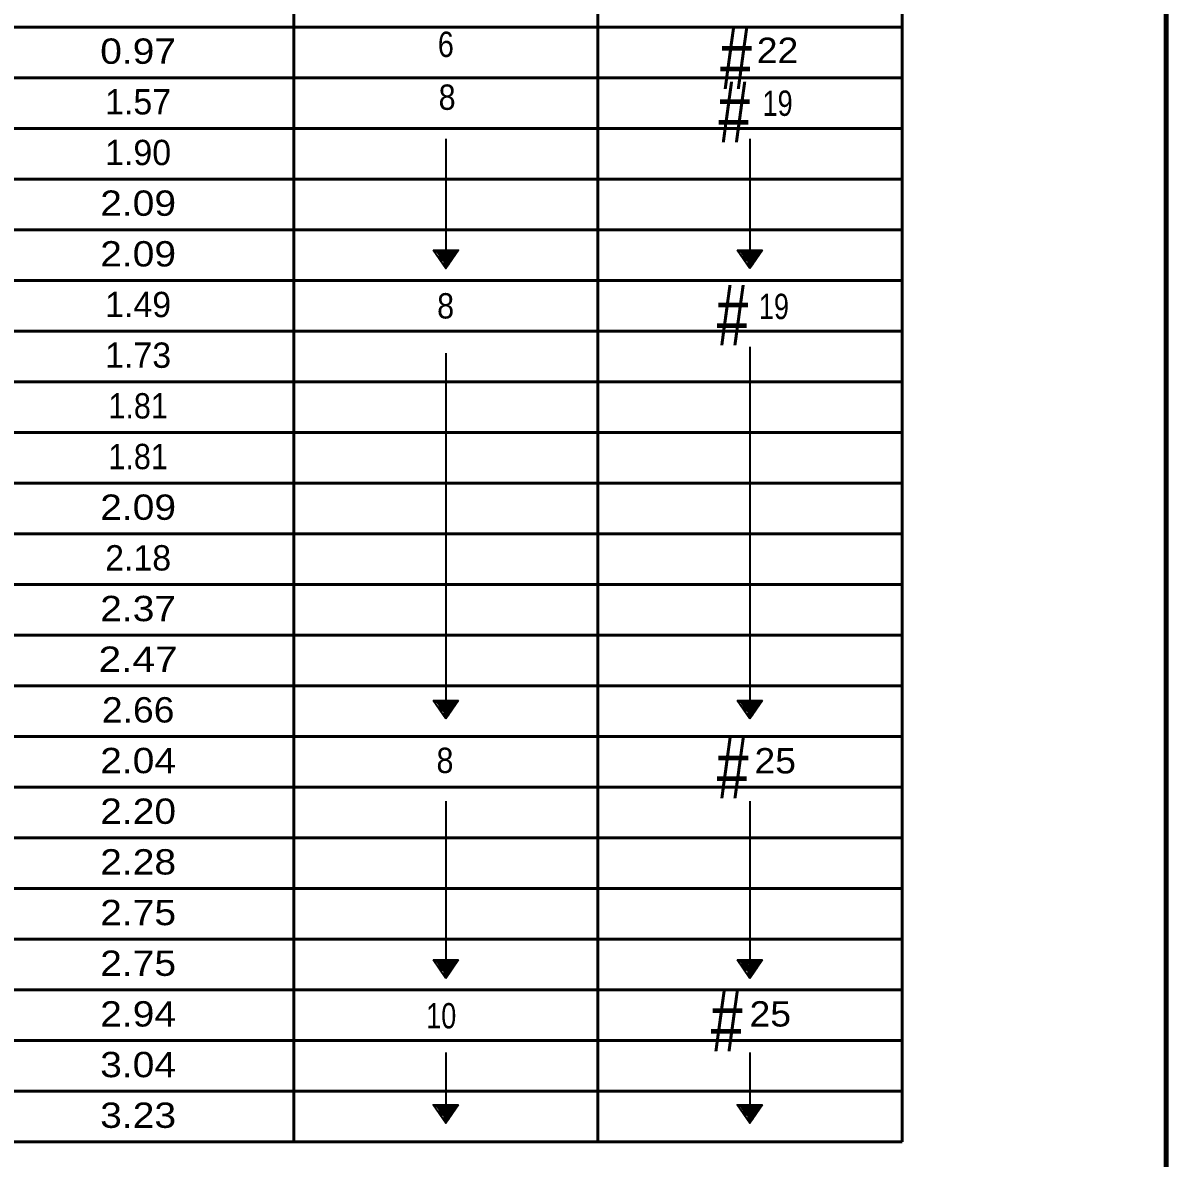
# Model space of a CAD drawing. Extents: x -711 to 145, y 25 to 569.
# Drawn here: x 13 to 138.1, y 280.2 to 404.4 of the extents above; entities that cross this region are included whole.
import ezdxf
from ezdxf.enums import TextEntityAlignment as Align

# ---------------------------------------------------------------- set-up
doc = ezdxf.new("R2010")
doc.units = 0
doc.header["$LTSCALE"] = 1.1
doc.layers.add('1', color=7, linetype='Continuous', lineweight=53)

msp = doc.modelspace()

# ---------------------------------------------------------------- linework, layer by layer
at = {"layer": '1', "lineweight": 158}
msp.add_line((138.105, 36.575), (138.105, 562.675), dxfattribs=at)
at = {"layer": '1', "lineweight": 13}
msp.add_line((138.105, 36.575), (138.105, 562.675), dxfattribs=at)
at = {"layer": '1'}
for p, q in [((42.685, 521.717), (42.685, 281.939)), ((109.213, 521.717), (109.213, 281.939)), ((75.949, 509.936), (75.949, 281.939)), ((-251.147, 403.907), (109.194, 403.907)), ((-251.147, 398.363), (109.194, 398.363)), ((-251.147, 392.819), (109.194, 392.819)), ((-251.147, 387.275), (109.194, 387.275)), ((-251.147, 381.731), (109.194, 381.731)), ((-251.147, 376.187), (109.194, 376.187)), ((-251.147, 370.643), (109.194, 370.643)), ((-251.147, 365.099), (109.194, 365.099)), ((-251.147, 359.555), (109.194, 359.555)), ((-251.147, 354.011), (109.194, 354.011)), ((-251.147, 348.467), (109.194, 348.467)), ((-251.147, 342.923), (109.194, 342.923)), ((-251.147, 337.379), (109.194, 337.379)), ((-251.147, 331.835), (109.194, 331.835)), ((-251.147, 326.291), (109.194, 326.291)), ((-251.147, 320.747), (109.194, 320.747)), ((-251.147, 315.203), (109.194, 315.203)), ((-251.147, 309.659), (109.194, 309.659)), ((-251.147, 304.115), (109.194, 304.115)), ((-251.147, 298.571), (109.194, 298.571)), ((-251.147, 293.027), (109.194, 293.027)), ((-251.147, 287.483), (109.194, 287.483)), ((-251.147, 281.939), (109.213, 281.939))]:
    msp.add_line(p, q, dxfattribs=at)
at = {"layer": '1', "lineweight": 35}
for p, q in [((59.317, 391.691), (59.317, 377.505)), ((92.581, 391.691), (92.581, 377.505)), ((91.195, 379.518), (93.967, 379.518)), ((92.581, 377.505), (91.195, 379.518)), ((93.967, 379.518), (92.581, 377.505)), ((92.581, 368.941), (92.581, 328.233)), ((59.317, 368.222), (59.317, 328.233)), ((57.931, 330.246), (60.703, 330.246)), ((59.317, 328.233), (57.931, 330.246)), ((60.703, 330.246), (59.317, 328.233)), ((91.195, 330.246), (93.967, 330.246)), ((92.581, 328.233), (91.195, 330.246)), ((93.967, 330.246), (92.581, 328.233)), ((59.317, 319.202), (59.317, 301.842)), ((92.581, 319.202), (92.581, 299.829)), ((59.317, 299.829), (57.931, 301.842)), ((57.931, 301.842), (60.703, 301.842)), ((60.703, 301.842), (59.317, 299.829)), ((92.581, 299.829), (91.195, 301.842)), ((91.195, 301.842), (93.967, 301.842)), ((93.967, 301.842), (92.581, 299.829)), ((59.317, 291.713), (59.317, 283.99)), ((92.581, 291.713), (92.581, 283.99))]:
    msp.add_line(p, q, dxfattribs=at)
for points in [[(57.931, 379.518), (60.703, 379.518), (59.317, 377.505)], [(60.703, 286.003), (59.317, 283.99), (57.931, 286.003)], [(93.967, 286.003), (92.581, 283.99), (91.195, 286.003)]]:
    msp.add_lwpolyline(points, close=True, dxfattribs=at)
for points in [[(58.19, 379.32), (58.614, 379.367), (59.273, 379.226), (59.744, 379.32), (59.933, 379.32), (60.216, 379.414), (60.404, 379.367), (59.556, 379.179), (59.179, 379.508), (59.226, 379.179), (59.226, 379.273), (59.65, 379.414), (60.168, 379.414), (60.074, 379.32), (59.085, 379.367), (58.708, 379.32), (58.473, 379.226), (58.661, 379.084), (58.755, 378.896), (58.849, 378.707), (58.896, 378.566), (59.038, 378.378), (59.462, 378.048), (59.462, 377.765), (59.32, 378.048), (59.226, 378.283), (59.038, 378.519), (58.849, 378.755), (58.567, 378.99), (58.378, 379.32), (58.567, 379.037), (58.661, 378.707), (58.802, 378.519), (58.896, 378.425), (59.132, 378.283), (59.273, 378.189), (59.367, 378.001), (59.415, 377.954), (59.273, 378.001), (59.132, 378.236), (59.132, 378.001), (59.65, 378.142), (60.357, 379.367), (60.404, 379.367), (60.357, 379.179), (60.168, 378.849), (59.98, 378.566), (59.933, 378.566), (59.744, 378.236), (59.603, 377.954), (59.462, 377.765), (59.367, 377.765), (60.451, 379.367), (60.404, 379.226), (60.545, 379.32), (60.357, 379.084), (60.074, 378.755), (59.933, 378.66), (59.744, 378.331), (59.65, 378.283), (59.509, 378.472), (59.32, 378.472), (59.132, 378.472), (59.462, 378.189), (59.415, 378.331), (59.179, 378.189), (59.65, 378.802), (59.556, 378.613), (59.509, 378.519), (59.32, 378.519), (59.132, 378.66), (59.085, 378.943), (58.991, 379.037), (58.896, 379.131), (59.367, 379.273), (59.556, 378.99), (59.603, 379.084), (59.226, 378.896), (59.462, 378.943), (59.744, 379.131), (59.839, 379.037), (59.509, 378.755), (59.509, 379.037), (59.32, 379.226), (58.896, 379.084), (58.802, 378.519), (59.367, 378.99), (59.603, 378.943), (59.744, 379.037), (59.886, 379.179), (59.697, 378.707), (59.65, 378.425), (59.98, 378.849), (59.744, 378.802), (60.027, 379.179), (59.886, 378.99), (59.839, 378.943), (59.556, 378.66), (59.509, 378.707), (59.415, 378.896), (59.367, 379.131)], [(59.367, 379.131), (59.038, 378.896), (59.226, 378.755), (58.661, 379.084), (58.661, 379.179), (58.943, 378.707), (59.415, 378.755), (59.179, 378.613), (59.462, 378.66), (59.886, 379.084), (60.121, 379.131), (60.121, 379.179), (59.98, 378.896), (59.556, 378.378), (59.462, 378.001), (58.755, 379.131), (58.755, 379.32), (58.849, 379.131), (58.755, 378.566), (59.273, 378.283), (59.085, 377.812), (59.32, 377.907), (59.132, 378.519), (59.744, 379.131), (59.226, 378.99)], [(91.454, 379.32), (91.878, 379.367), (92.537, 379.226), (93.008, 379.32), (93.197, 379.32), (93.48, 379.414), (93.668, 379.367), (92.82, 379.179), (92.443, 379.508), (92.49, 379.179), (92.49, 379.273), (92.914, 379.414), (93.432, 379.414), (93.338, 379.32), (92.349, 379.367), (91.972, 379.32), (91.737, 379.226), (91.925, 379.084), (92.019, 378.896), (92.113, 378.707), (92.16, 378.566), (92.302, 378.378), (92.726, 378.048), (92.726, 377.765), (92.584, 378.048), (92.49, 378.283), (92.302, 378.519), (92.113, 378.755), (91.831, 378.99), (91.642, 379.32), (91.831, 379.037), (91.925, 378.707), (92.066, 378.519), (92.16, 378.425), (92.396, 378.283), (92.537, 378.189), (92.631, 378.001), (92.679, 377.954), (92.537, 378.001), (92.396, 378.236), (92.396, 378.001), (92.914, 378.142), (93.621, 379.367), (93.668, 379.367), (93.621, 379.179), (93.432, 378.849), (93.244, 378.566), (93.197, 378.566), (93.008, 378.236), (92.867, 377.954), (92.726, 377.765), (92.631, 377.765), (93.715, 379.367), (93.668, 379.226), (93.809, 379.32), (93.621, 379.084), (93.338, 378.755), (93.197, 378.66), (93.008, 378.331), (92.914, 378.283), (92.773, 378.472), (92.584, 378.472), (92.396, 378.472), (92.726, 378.189), (92.679, 378.331), (92.443, 378.189), (92.914, 378.802), (92.82, 378.613), (92.773, 378.519), (92.584, 378.519), (92.396, 378.66), (92.349, 378.943), (92.255, 379.037), (92.16, 379.131), (92.631, 379.273), (92.82, 378.99), (92.867, 379.084), (92.49, 378.896), (92.726, 378.943), (93.008, 379.131), (93.103, 379.037), (92.773, 378.755), (92.773, 379.037), (92.584, 379.226), (92.16, 379.084), (92.066, 378.519), (92.631, 378.99), (92.867, 378.943), (93.008, 379.037), (93.15, 379.179), (92.961, 378.707), (92.914, 378.425), (93.244, 378.849), (93.008, 378.802), (93.291, 379.179), (93.15, 378.99), (93.103, 378.943), (92.82, 378.66), (92.773, 378.707), (92.679, 378.896), (92.631, 379.131)], [(92.631, 379.131), (92.302, 378.896), (92.49, 378.755), (91.925, 379.084), (91.925, 379.179), (92.207, 378.707), (92.679, 378.755), (92.443, 378.613), (92.726, 378.66), (93.15, 379.084), (93.385, 379.131), (93.385, 379.179), (93.244, 378.896), (92.82, 378.378), (92.726, 378.001), (92.019, 379.131), (92.019, 379.32), (92.113, 379.131), (92.019, 378.566), (92.537, 378.283), (92.349, 377.812), (92.584, 377.907), (92.396, 378.519), (93.008, 379.131), (92.49, 378.99)], [(58.19, 330.048), (58.614, 330.095), (59.273, 329.954), (59.744, 330.048), (59.933, 330.048), (60.216, 330.142), (60.404, 330.095), (59.556, 329.907), (59.179, 330.236), (59.226, 329.907), (59.226, 330.001), (59.65, 330.142), (60.168, 330.142), (60.074, 330.048), (59.085, 330.095), (58.708, 330.048), (58.473, 329.954), (58.661, 329.812), (58.755, 329.624), (58.849, 329.435), (58.896, 329.294), (59.038, 329.106), (59.462, 328.776), (59.462, 328.493), (59.32, 328.776), (59.226, 329.011), (59.038, 329.247), (58.849, 329.483), (58.567, 329.718), (58.378, 330.048), (58.567, 329.765), (58.661, 329.435), (58.802, 329.247), (58.896, 329.153), (59.132, 329.011), (59.273, 328.917), (59.367, 328.729), (59.415, 328.682), (59.273, 328.729), (59.132, 328.964), (59.132, 328.729), (59.65, 328.87), (60.357, 330.095), (60.404, 330.095), (60.357, 329.907), (60.168, 329.577), (59.98, 329.294), (59.933, 329.294), (59.744, 328.964), (59.603, 328.682), (59.462, 328.493), (59.367, 328.493), (60.451, 330.095), (60.404, 329.954), (60.545, 330.048), (60.357, 329.812), (60.074, 329.483), (59.933, 329.388), (59.744, 329.059), (59.65, 329.011), (59.509, 329.2), (59.32, 329.2), (59.132, 329.2), (59.462, 328.917), (59.415, 329.059), (59.179, 328.917), (59.65, 329.53), (59.556, 329.341), (59.509, 329.247), (59.32, 329.247), (59.132, 329.388), (59.085, 329.671), (58.991, 329.765), (58.896, 329.859), (59.367, 330.001), (59.556, 329.718), (59.603, 329.812), (59.226, 329.624), (59.462, 329.671), (59.744, 329.859), (59.839, 329.765), (59.509, 329.483), (59.509, 329.765), (59.32, 329.954), (58.896, 329.812), (58.802, 329.247), (59.367, 329.718), (59.603, 329.671), (59.744, 329.765), (59.886, 329.907), (59.697, 329.435), (59.65, 329.153), (59.98, 329.577), (59.744, 329.53), (60.027, 329.907), (59.886, 329.718), (59.839, 329.671), (59.556, 329.388), (59.509, 329.435), (59.415, 329.624), (59.367, 329.859)], [(91.454, 330.048), (91.878, 330.095), (92.537, 329.954), (93.008, 330.048), (93.197, 330.048), (93.48, 330.142), (93.668, 330.095), (92.82, 329.907), (92.443, 330.236), (92.49, 329.907), (92.49, 330.001), (92.914, 330.142), (93.432, 330.142), (93.338, 330.048), (92.349, 330.095), (91.972, 330.048), (91.737, 329.954), (91.925, 329.812), (92.019, 329.624), (92.113, 329.435), (92.16, 329.294), (92.302, 329.106), (92.726, 328.776), (92.726, 328.493), (92.584, 328.776), (92.49, 329.011), (92.302, 329.247), (92.113, 329.483), (91.831, 329.718), (91.642, 330.048), (91.831, 329.765), (91.925, 329.435), (92.066, 329.247), (92.16, 329.153), (92.396, 329.011), (92.537, 328.917), (92.631, 328.729), (92.679, 328.682), (92.537, 328.729), (92.396, 328.964), (92.396, 328.729), (92.914, 328.87), (93.621, 330.095), (93.668, 330.095), (93.621, 329.907), (93.432, 329.577), (93.244, 329.294), (93.197, 329.294), (93.008, 328.964), (92.867, 328.682), (92.726, 328.493), (92.631, 328.493), (93.715, 330.095), (93.668, 329.954), (93.809, 330.048), (93.621, 329.812), (93.338, 329.483), (93.197, 329.388), (93.008, 329.059), (92.914, 329.011), (92.773, 329.2), (92.584, 329.2), (92.396, 329.2), (92.726, 328.917), (92.679, 329.059), (92.443, 328.917), (92.914, 329.53), (92.82, 329.341), (92.773, 329.247), (92.584, 329.247), (92.396, 329.388), (92.349, 329.671), (92.255, 329.765), (92.16, 329.859), (92.631, 330.001), (92.82, 329.718), (92.867, 329.812), (92.49, 329.624), (92.726, 329.671), (93.008, 329.859), (93.103, 329.765), (92.773, 329.483), (92.773, 329.765), (92.584, 329.954), (92.16, 329.812), (92.066, 329.247), (92.631, 329.718), (92.867, 329.671), (93.008, 329.765), (93.15, 329.907), (92.961, 329.435), (92.914, 329.153), (93.244, 329.577), (93.008, 329.53), (93.291, 329.907), (93.15, 329.718), (93.103, 329.671), (92.82, 329.388), (92.773, 329.435), (92.679, 329.624), (92.631, 329.859)], [(59.367, 329.859), (59.038, 329.624), (59.226, 329.483), (58.661, 329.812), (58.661, 329.907), (58.943, 329.435), (59.415, 329.483), (59.179, 329.341), (59.462, 329.388), (59.886, 329.812), (60.121, 329.859), (60.121, 329.907), (59.98, 329.624), (59.556, 329.106), (59.462, 328.729), (58.755, 329.859), (58.755, 330.048), (58.849, 329.859), (58.755, 329.294), (59.273, 329.011), (59.085, 328.54), (59.32, 328.635), (59.132, 329.247), (59.744, 329.859), (59.226, 329.718)], [(92.631, 329.859), (92.302, 329.624), (92.49, 329.483), (91.925, 329.812), (91.925, 329.907), (92.207, 329.435), (92.679, 329.483), (92.443, 329.341), (92.726, 329.388), (93.15, 329.812), (93.385, 329.859), (93.385, 329.907), (93.244, 329.624), (92.82, 329.106), (92.726, 328.729), (92.019, 329.859), (92.019, 330.048), (92.113, 329.859), (92.019, 329.294), (92.537, 329.011), (92.349, 328.54), (92.584, 328.635), (92.396, 329.247), (93.008, 329.859), (92.49, 329.718)], [(58.19, 301.643), (58.614, 301.69), (59.273, 301.549), (59.744, 301.643), (59.933, 301.643), (60.216, 301.738), (60.404, 301.69), (59.556, 301.502), (59.179, 301.832), (59.226, 301.502), (59.226, 301.596), (59.65, 301.738), (60.168, 301.738), (60.074, 301.643), (59.085, 301.69), (58.708, 301.643), (58.473, 301.549), (58.661, 301.408), (58.755, 301.219), (58.849, 301.031), (58.896, 300.89), (59.038, 300.701), (59.462, 300.371), (59.462, 300.089), (59.32, 300.371), (59.226, 300.607), (59.038, 300.842), (58.849, 301.078), (58.567, 301.314), (58.378, 301.643), (58.567, 301.361), (58.661, 301.031), (58.802, 300.842), (58.896, 300.748), (59.132, 300.607), (59.273, 300.513), (59.367, 300.324), (59.415, 300.277), (59.273, 300.324), (59.132, 300.56), (59.132, 300.324), (59.65, 300.466), (60.357, 301.69), (60.404, 301.69), (60.357, 301.502), (60.168, 301.172), (59.98, 300.89), (59.933, 300.89), (59.744, 300.56), (59.603, 300.277), (59.462, 300.089), (59.367, 300.089), (60.451, 301.69), (60.404, 301.549), (60.545, 301.643), (60.357, 301.408), (60.074, 301.078), (59.933, 300.984), (59.744, 300.654), (59.65, 300.607), (59.509, 300.795), (59.32, 300.795), (59.132, 300.795), (59.462, 300.513), (59.415, 300.654), (59.179, 300.513), (59.65, 301.125), (59.556, 300.937), (59.509, 300.842), (59.32, 300.842), (59.132, 300.984), (59.085, 301.266), (58.991, 301.361), (58.896, 301.455), (59.367, 301.596), (59.556, 301.314), (59.603, 301.408), (59.226, 301.219), (59.462, 301.266), (59.744, 301.455), (59.839, 301.361), (59.509, 301.078), (59.509, 301.361), (59.32, 301.549), (58.896, 301.408), (58.802, 300.842), (59.367, 301.314), (59.603, 301.266), (59.744, 301.361), (59.886, 301.502), (59.697, 301.031), (59.65, 300.748), (59.98, 301.172), (59.744, 301.125), (60.027, 301.502), (59.886, 301.314), (59.839, 301.266), (59.556, 300.984), (59.509, 301.031), (59.415, 301.219), (59.367, 301.455)], [(59.367, 301.455), (59.038, 301.219), (59.226, 301.078), (58.661, 301.408), (58.661, 301.502), (58.943, 301.031), (59.415, 301.078), (59.179, 300.937), (59.462, 300.984), (59.886, 301.408), (60.121, 301.455), (60.121, 301.502), (59.98, 301.219), (59.556, 300.701), (59.462, 300.324), (58.755, 301.455), (58.755, 301.643), (58.849, 301.455), (58.755, 300.89), (59.273, 300.607), (59.085, 300.136), (59.32, 300.23), (59.132, 300.842), (59.744, 301.455), (59.226, 301.314)], [(91.454, 301.643), (91.878, 301.69), (92.537, 301.549), (93.008, 301.643), (93.197, 301.643), (93.48, 301.738), (93.668, 301.69), (92.82, 301.502), (92.443, 301.832), (92.49, 301.502), (92.49, 301.596), (92.914, 301.738), (93.432, 301.738), (93.338, 301.643), (92.349, 301.69), (91.972, 301.643), (91.737, 301.549), (91.925, 301.408), (92.019, 301.219), (92.113, 301.031), (92.16, 300.89), (92.302, 300.701), (92.726, 300.371), (92.726, 300.089), (92.584, 300.371), (92.49, 300.607), (92.302, 300.842), (92.113, 301.078), (91.831, 301.314), (91.642, 301.643), (91.831, 301.361), (91.925, 301.031), (92.066, 300.842), (92.16, 300.748), (92.396, 300.607), (92.537, 300.513), (92.631, 300.324), (92.679, 300.277), (92.537, 300.324), (92.396, 300.56), (92.396, 300.324), (92.914, 300.466), (93.621, 301.69), (93.668, 301.69), (93.621, 301.502), (93.432, 301.172), (93.244, 300.89), (93.197, 300.89), (93.008, 300.56), (92.867, 300.277), (92.726, 300.089), (92.631, 300.089), (93.715, 301.69), (93.668, 301.549), (93.809, 301.643), (93.621, 301.408), (93.338, 301.078), (93.197, 300.984), (93.008, 300.654), (92.914, 300.607), (92.773, 300.795), (92.584, 300.795), (92.396, 300.795), (92.726, 300.513), (92.679, 300.654), (92.443, 300.513), (92.914, 301.125), (92.82, 300.937), (92.773, 300.842), (92.584, 300.842), (92.396, 300.984), (92.349, 301.266), (92.255, 301.361), (92.16, 301.455), (92.631, 301.596), (92.82, 301.314), (92.867, 301.408), (92.49, 301.219), (92.726, 301.266), (93.008, 301.455), (93.103, 301.361), (92.773, 301.078), (92.773, 301.361), (92.584, 301.549), (92.16, 301.408), (92.066, 300.842), (92.631, 301.314), (92.867, 301.266), (93.008, 301.361), (93.15, 301.502), (92.961, 301.031), (92.914, 300.748), (93.244, 301.172), (93.008, 301.125), (93.291, 301.502), (93.15, 301.314), (93.103, 301.266), (92.82, 300.984), (92.773, 301.031), (92.679, 301.219), (92.631, 301.455)], [(92.631, 301.455), (92.302, 301.219), (92.49, 301.078), (91.925, 301.408), (91.925, 301.502), (92.207, 301.031), (92.679, 301.078), (92.443, 300.937), (92.726, 300.984), (93.15, 301.408), (93.385, 301.455), (93.385, 301.502), (93.244, 301.219), (92.82, 300.701), (92.726, 300.324), (92.019, 301.455), (92.019, 301.643), (92.113, 301.455), (92.019, 300.89), (92.537, 300.607), (92.349, 300.136), (92.584, 300.23), (92.396, 300.842), (93.008, 301.455), (92.49, 301.314)], [(58.19, 285.805), (58.614, 285.852), (59.273, 285.711), (59.744, 285.805), (59.933, 285.805), (60.216, 285.899), (60.404, 285.852), (59.556, 285.663), (59.179, 285.993), (59.226, 285.663), (59.226, 285.758), (59.65, 285.899), (60.168, 285.899), (60.074, 285.805), (59.085, 285.852), (58.708, 285.805), (58.473, 285.711), (58.661, 285.569), (58.755, 285.381), (58.849, 285.192), (58.896, 285.051), (59.038, 284.863), (59.462, 284.533), (59.462, 284.25), (59.32, 284.533), (59.226, 284.768), (59.038, 285.004), (58.849, 285.239), (58.567, 285.475), (58.378, 285.805), (58.567, 285.522), (58.661, 285.192), (58.802, 285.004), (58.896, 284.91), (59.132, 284.768), (59.273, 284.674), (59.367, 284.486), (59.415, 284.439), (59.273, 284.486), (59.132, 284.721), (59.132, 284.486), (59.65, 284.627), (60.357, 285.852), (60.404, 285.852), (60.357, 285.663), (60.168, 285.334), (59.98, 285.051), (59.933, 285.051), (59.744, 284.721), (59.603, 284.439), (59.462, 284.25), (59.367, 284.25), (60.451, 285.852), (60.404, 285.711), (60.545, 285.805), (60.357, 285.569), (60.074, 285.239), (59.933, 285.145), (59.744, 284.815), (59.65, 284.768), (59.509, 284.957), (59.32, 284.957), (59.132, 284.957), (59.462, 284.674), (59.415, 284.815), (59.179, 284.674), (59.65, 285.287), (59.556, 285.098), (59.509, 285.004), (59.32, 285.004), (59.132, 285.145), (59.085, 285.428), (58.991, 285.522), (58.896, 285.616), (59.367, 285.758), (59.556, 285.475), (59.603, 285.569), (59.226, 285.381), (59.462, 285.428), (59.744, 285.616), (59.839, 285.522), (59.509, 285.239), (59.509, 285.522), (59.32, 285.711), (58.896, 285.569), (58.802, 285.004), (59.367, 285.475), (59.603, 285.428), (59.744, 285.522), (59.886, 285.663), (59.697, 285.192), (59.65, 284.91), (59.98, 285.334), (59.744, 285.287), (60.027, 285.663), (59.886, 285.475), (59.839, 285.428), (59.556, 285.145), (59.509, 285.192), (59.415, 285.381), (59.367, 285.616)], [(59.367, 285.616), (59.038, 285.381), (59.226, 285.239), (58.661, 285.569), (58.661, 285.663), (58.943, 285.192), (59.415, 285.239), (59.179, 285.098), (59.462, 285.145), (59.886, 285.569), (60.121, 285.616), (60.121, 285.663), (59.98, 285.381), (59.556, 284.863), (59.462, 284.486), (58.755, 285.616), (58.755, 285.805), (58.849, 285.616), (58.755, 285.051), (59.273, 284.768), (59.085, 284.297), (59.32, 284.392), (59.132, 285.004), (59.744, 285.616), (59.226, 285.475)], [(91.454, 285.805), (91.878, 285.852), (92.537, 285.711), (93.008, 285.805), (93.197, 285.805), (93.48, 285.899), (93.668, 285.852), (92.82, 285.663), (92.443, 285.993), (92.49, 285.663), (92.49, 285.758), (92.914, 285.899), (93.432, 285.899), (93.338, 285.805), (92.349, 285.852), (91.972, 285.805), (91.737, 285.711), (91.925, 285.569), (92.019, 285.381), (92.113, 285.192), (92.16, 285.051), (92.302, 284.863), (92.726, 284.533), (92.726, 284.25), (92.584, 284.533), (92.49, 284.768), (92.302, 285.004), (92.113, 285.239), (91.831, 285.475), (91.642, 285.805), (91.831, 285.522), (91.925, 285.192), (92.066, 285.004), (92.16, 284.91), (92.396, 284.768), (92.537, 284.674), (92.631, 284.486), (92.679, 284.439), (92.537, 284.486), (92.396, 284.721), (92.396, 284.486), (92.914, 284.627), (93.621, 285.852), (93.668, 285.852), (93.621, 285.663), (93.432, 285.334), (93.244, 285.051), (93.197, 285.051), (93.008, 284.721), (92.867, 284.439), (92.726, 284.25), (92.631, 284.25), (93.715, 285.852), (93.668, 285.711), (93.809, 285.805), (93.621, 285.569), (93.338, 285.239), (93.197, 285.145), (93.008, 284.815), (92.914, 284.768), (92.773, 284.957), (92.584, 284.957), (92.396, 284.957), (92.726, 284.674), (92.679, 284.815), (92.443, 284.674), (92.914, 285.287), (92.82, 285.098), (92.773, 285.004), (92.584, 285.004), (92.396, 285.145), (92.349, 285.428), (92.255, 285.522), (92.16, 285.616), (92.631, 285.758), (92.82, 285.475), (92.867, 285.569), (92.49, 285.381), (92.726, 285.428), (93.008, 285.616), (93.103, 285.522), (92.773, 285.239), (92.773, 285.522), (92.584, 285.711), (92.16, 285.569), (92.066, 285.004), (92.631, 285.475), (92.867, 285.428), (93.008, 285.522), (93.15, 285.663), (92.961, 285.192), (92.914, 284.91), (93.244, 285.334), (93.008, 285.287), (93.291, 285.663), (93.15, 285.475), (93.103, 285.428), (92.82, 285.145), (92.773, 285.192), (92.679, 285.381), (92.631, 285.616)], [(92.631, 285.616), (92.302, 285.381), (92.49, 285.239), (91.925, 285.569), (91.925, 285.663), (92.207, 285.192), (92.679, 285.239), (92.443, 285.098), (92.726, 285.145), (93.15, 285.569), (93.385, 285.616), (93.385, 285.663), (93.244, 285.381), (92.82, 284.863), (92.726, 284.486), (92.019, 285.616), (92.019, 285.805), (92.113, 285.616), (92.019, 285.051), (92.537, 284.768), (92.349, 284.297), (92.584, 284.392), (92.396, 285.004), (93.008, 285.616), (92.49, 285.475)]]:
    msp.add_lwpolyline(points, dxfattribs=at)

# ---------------------------------------------------------------- texts
at = {"layer": '1'}
for s, height, width, p in [('0.97', 2.772, 1.15, (25.654, 399.897)), ('6', 2.772, 0.85, (59.312, 400.644)), ('#', 6.653, 0.7, (91.054, 397.143)), ('22', 2.772, 1.1, (95.599, 399.99)), ('#', 6.653, 0.7, (90.849, 391.321)), ('8', 2.772, 0.9, (59.453, 394.861)), ('19', 2.772, 0.8, (95.605, 394.202)), ('2.09', 2.772, 1.15, (25.654, 383.265)), ('2.09', 2.772, 1.15, (25.654, 377.721)), ('#', 6.653, 0.7, (90.679, 369.082)), ('8', 2.772, 0.9, (59.289, 372.029)), ('19', 2.772, 0.8, (95.2, 371.967)), ('1.81', 2.772, 0.9, (25.654, 361.089)), ('1.81', 2.772, 0.9, (25.654, 355.545)), ('2.09', 2.772, 1.15, (25.654, 350.001)), ('2.37', 2.772, 1.15, (25.654, 338.913)), ('2.47', 2.772, 1.2, (25.654, 333.369)), ('2.66', 2.772, 1.1, (25.654, 327.825)), ('#', 6.653, 0.7, (90.684, 319.512)), ('2.04', 2.772, 1.15, (25.654, 322.281)), ('8', 2.772, 0.9, (59.219, 322.295)), ('25', 2.772, 1.1, (95.343, 322.255)), ('2.20', 2.772, 1.15, (25.654, 316.737)), ('2.28', 2.772, 1.15, (25.654, 311.193)), ('2.75', 2.772, 1.15, (25.654, 305.649)), ('2.75', 2.772, 1.15, (25.654, 300.105)), ('#', 6.653, 0.7, (90.039, 291.855)), ('2.94', 2.772, 1.15, (25.654, 294.561)), ('10', 2.772, 0.8, (58.806, 294.356)), ('25', 2.772, 1.1, (94.803, 294.561)), ('3.04', 2.772, 1.15, (25.654, 289.017)), ('3.23', 2.772, 1.15, (25.654, 283.473))]:
    msp.add_text(s, height=height, dxfattribs=dict(at, width=width)).set_placement(p, align=Align.CENTER)
for s, p in [('1.57', (25.654, 394.353)), ('1.90', (25.654, 388.809)), ('1.49', (25.654, 372.177)), ('1.73', (25.654, 366.633)), ('2.18', (25.654, 344.457))]:
    msp.add_text(s, height=2.772, dxfattribs=at).set_placement(p, align=Align.CENTER)

doc.saveas('drawing.dxf')
